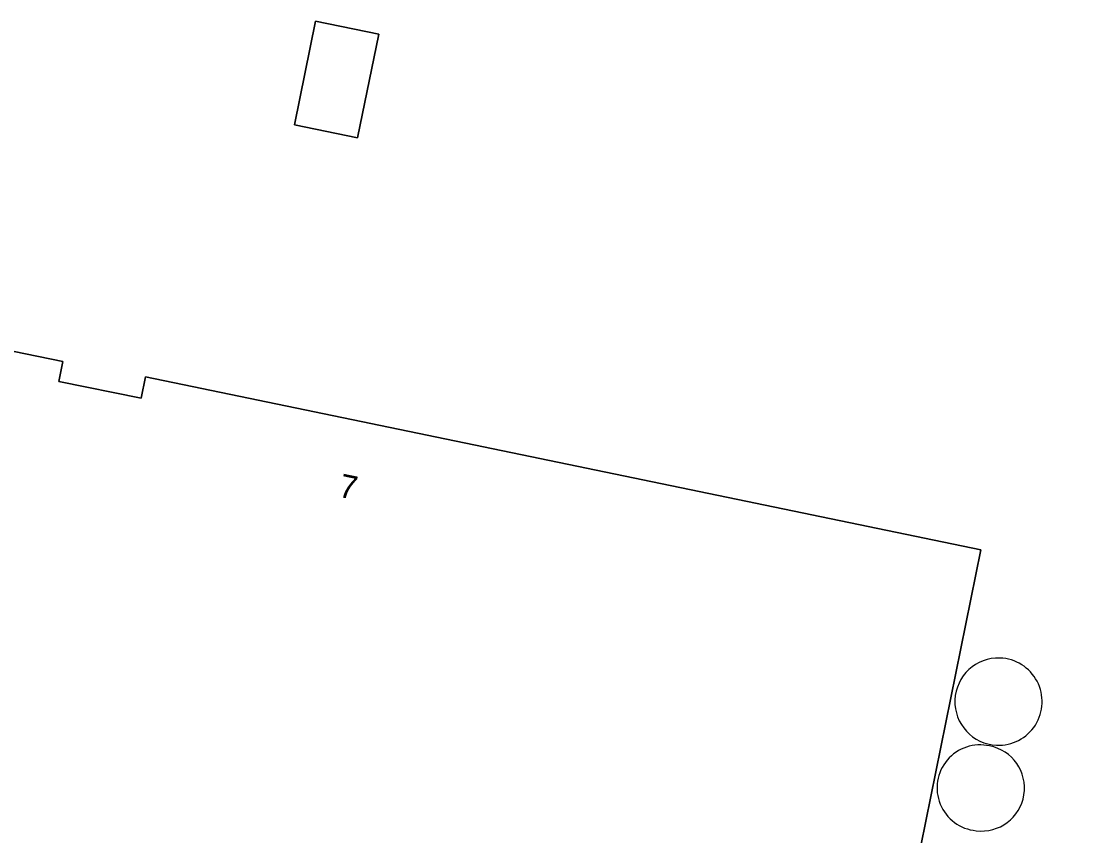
# Model space of a CAD drawing. Extents: x 157692 to 159674, y 381452 to 383291.
# Drawn here: x 158207.7 to 158253, y 382096.94 to 382131.64 of the extents above; entities that cross this region are included whole.
import ezdxf

# ---------------------------------------------------------------- set-up
doc = ezdxf.new("R2010")
doc.units = 0
for name, color, linetype in [('IMGEO_Erf', 7, 'Continuous'), ('IMGEO_Opslagtank', 7, 'Continuous'), ('IMGEO_Pand', 7, 'Continuous'), ('IMGEO_Pand_nummerreeks', 7, 'Continuous')]:
    doc.layers.add(name, color=color, linetype=linetype)

msp = doc.modelspace()

# ---------------------------------------------------------------- linework, layer by layer
at = {"layer": 'IMGEO_Erf'}
msp.add_lwpolyline([(158219.347, 382127.228), (158220.253, 382131.644), (158222.948, 382131.091), (158222.042, 382126.675)], close=True, dxfattribs=at)
msp.add_lwpolyline([(158195.616, 382119.984), (158209.48, 382117.149), (158209.306, 382116.294), (158212.818, 382115.576), (158213.006, 382116.497), (158248.612, 382109.118), (158243.063, 382081.789), (158249.106, 382080.544), (158248.299, 382076.625), (158253, 382075.656), (158251.991, 382070.759), (158251.244, 382067.135), (158243.889, 382068.651), (158243.147, 382065.047), (158242.296, 382060.912), (158238.924, 382061.607), (158219.306, 382065.65), (158217.658, 382057.871), (158202.03, 382061.091)], dxfattribs=at)
for centre, radius, start, end in [((158249.364, 382102.65), 1.858, 87.9112, 267.462), ((158249.368, 382102.65), 1.858, 267.3464, 88.0268), ((158248.576, 382098.976), 1.832, 77.1012, 264.7727), ((158248.644, 382098.965), 1.829, 262.6333, 79.2406)]:
    msp.add_arc(centre, radius, start, end, dxfattribs=at)
at = {"layer": 'IMGEO_Opslagtank'}
for centre, radius, start, end in [((158249.364, 382102.65), 1.858, 87.9112, 267.462), ((158249.368, 382102.65), 1.858, 267.3464, 88.0268), ((158248.576, 382098.976), 1.832, 77.1012, 264.7727), ((158248.644, 382098.965), 1.829, 262.6333, 79.2406)]:
    msp.add_arc(centre, radius, start, end, dxfattribs=at)
at = {"layer": 'IMGEO_Pand'}
msp.add_lwpolyline([(158219.347, 382127.228), (158222.042, 382126.675), (158222.948, 382131.091), (158220.253, 382131.644)], close=True, dxfattribs=at)
msp.add_lwpolyline([(158202.03, 382061.091), (158217.658, 382057.871), (158219.306, 382065.65), (158238.924, 382061.607), (158242.296, 382060.912), (158243.147, 382065.047), (158243.889, 382068.651), (158251.244, 382067.135), (158251.991, 382070.759), (158253, 382075.656), (158248.299, 382076.625), (158249.106, 382080.544), (158243.063, 382081.789), (158248.612, 382109.118), (158213.006, 382116.497), (158212.818, 382115.576), (158209.306, 382116.294), (158209.48, 382117.149), (158195.616, 382119.984)], dxfattribs=at)

# ---------------------------------------------------------------- texts
at = {"layer": 'IMGEO_Pand_nummerreeks'}
msp.add_text('7', height=1, rotation=348.4148, dxfattribs=at).set_placement((158221.186, 382111.393))

doc.saveas('drawing.dxf')
